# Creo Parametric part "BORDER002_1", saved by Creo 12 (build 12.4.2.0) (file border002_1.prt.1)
Units: Custom; MM, KILOGRAM, SECS

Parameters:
  PTC_WM_ITERATION = "0"
  PTC_WM_VERSION = "-.0"
  PTC_WM_LIFECYCLE_STATE = "In Work"
  PTC_WM_LIFECYCLE = "MO_CADDocument"
  PTC_WM_CREATED_BY = "Maximilian Roepper (Z0017RMS: MO)"
  PTC_WM_CREATED_ON = "18-Sep-26 11:36:42 AM"
  PTC_WM_MODIFIED_BY = "Maximilian Roepper (Z0017RMS: MO)"
  PTC_WM_MODIFIED_ON = "18-Sep-26 11:36:46 AM"
  PDMLINKNUMBER = "PDM000071455237"
  PTC_WM_NAME = "border002_1.prt"
  PTC_WM_NUMBER = "PDM000071455237"

Other parameters: WEIGHT, WEIGHT_FACTOR, WEIGHT_ADD, _MASS_TEMP, _DIFF_TEMP, MC_ERRORS, SUPPLIER

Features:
  1. coordinate system
  2. datum plane "PRT_YZ"
  3. datum plane "PRT_XY"
  4. datum plane "PRT_XZ"
  5. coordinate system
  6. datum axis
  7. datum axis
  8. datum axis
  9. coordinate system
  10. imported feature

Other named items: PRT, SIEMENS_MO, DRW_VIEW_ORG, PRT_X, PRT_Y, PRT_Z, CS0, ROUGH_GROB

Layers: 00_STD_CSYS-KSYS, 01_STD_PLANES-EBENEN, 02_STD_AXES-ACHSEN, 03_STD_CSYS-KSYS, 24_IMPORT_FEAT-IMPORT_KE

Surfaces: 2 plane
